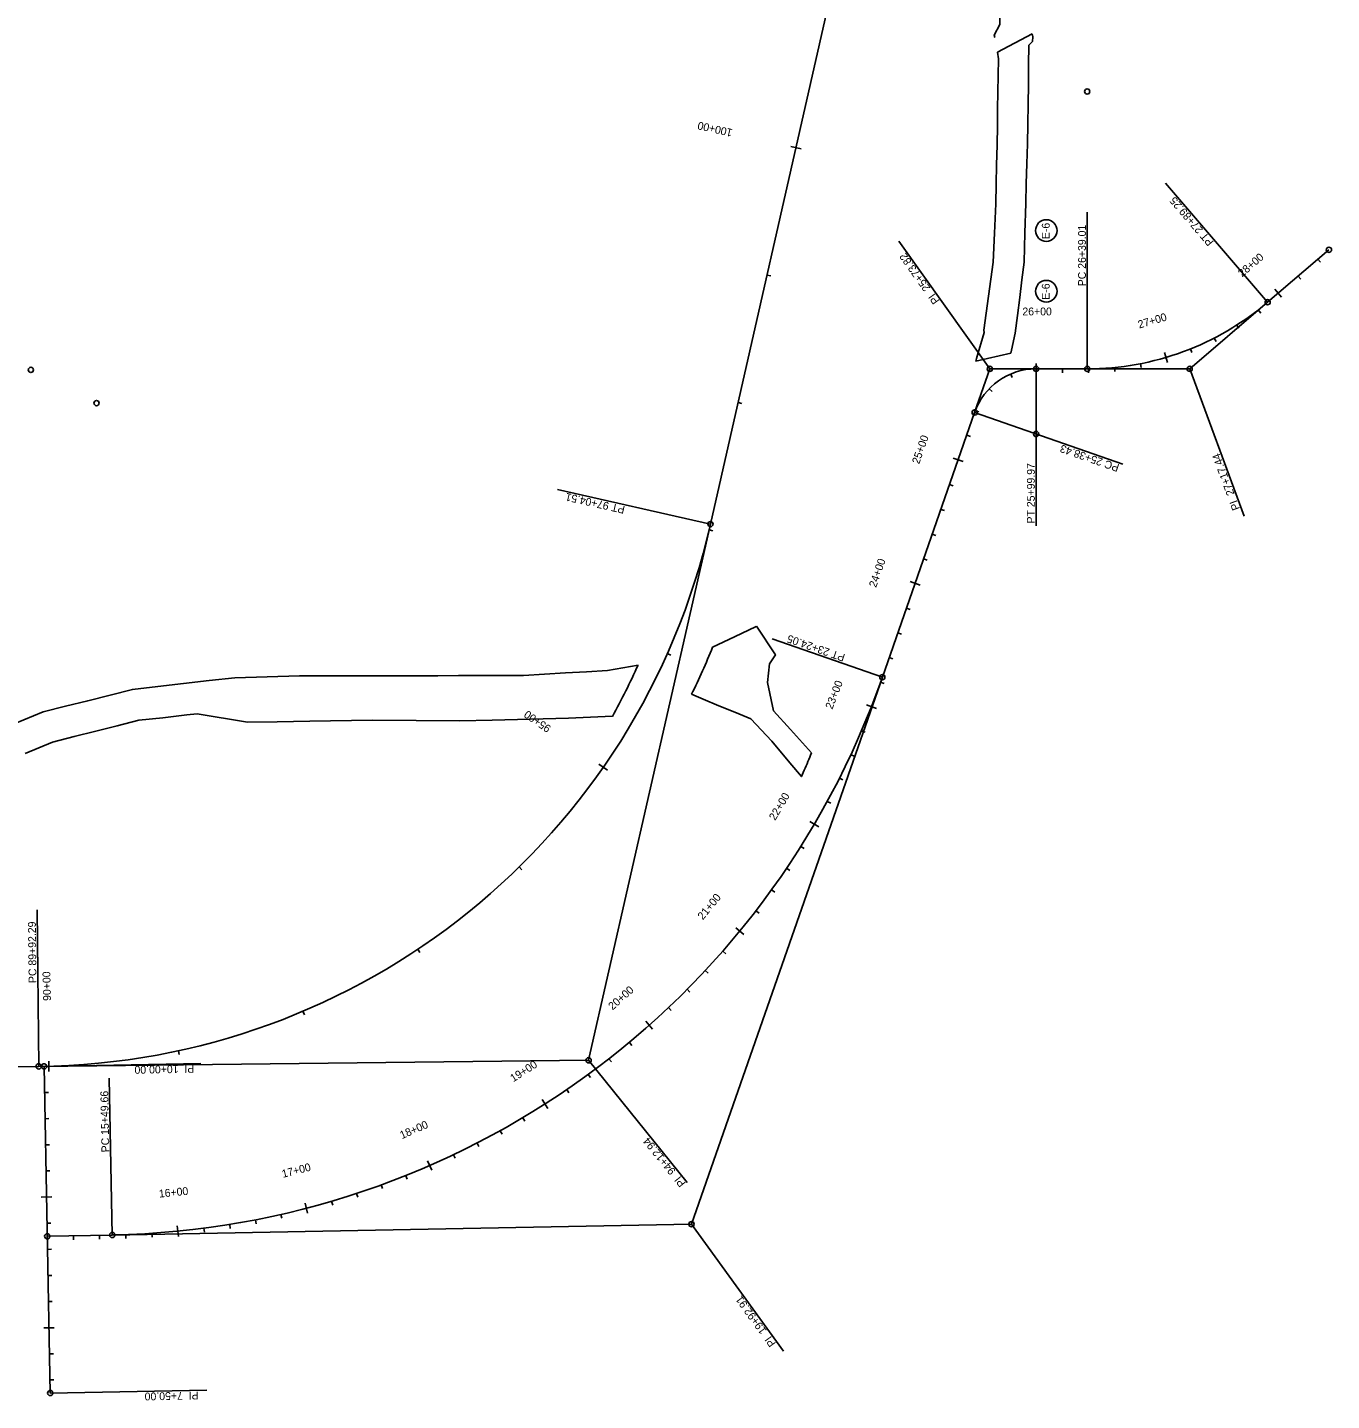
# Model space of a CAD drawing. Extents: x 1710760 to 1712722, y 548603 to 551099.
# Drawn here: x 1711724 to 1712722, y 548957 to 550007 of the extents above; entities that cross this region are included whole.
import ezdxf

# ---------------------------------------------------------------- set-up
doc = ezdxf.new("R2010")
doc.units = 0
for name, color, linetype in [('R_Draft', 7, 'Continuous'), ('R_Erosion', 7, 'Continuous'), ('R_Horz Alg', 7, 'Continuous'), ('R_Horz Alg Annot', 7, 'Continuous')]:
    doc.layers.add(name, color=color, linetype=linetype)

msp = doc.modelspace()

# ---------------------------------------------------------------- linework, layer by layer
at = {"layer": 'R_Draft'}
msp.add_line((1712466.4, 549988.4), (1712492.8, 550002.3), dxfattribs=at)
for points in [[(1712467.8, 550127.2), (1712467.8, 550116.5), (1712467.5, 550095.6), (1712466.2, 550089.2), (1712466.5, 550075.5), (1712466.7, 550061.9), (1712467.1, 550048.8), (1712467.4, 550035.7), (1712467.8, 550022.6), (1712468.1, 550009.5), (1712463.8, 550001.4), (1712464.3, 549999.7)], [(1712492.8, 550002.3), (1712493.5, 550000), (1712493.1, 549996.5), (1712490.4, 549993.8), (1712490.2, 549978.7), (1712490, 549963.6), (1712489.9, 549948.5), (1712489.7, 549933.4), (1712489.3, 549918.2), (1712488.9, 549903), (1712488.4, 549887.9), (1712488, 549872.7), (1712487.4, 549850.2), (1712486.8, 549827.8), (1712485.1, 549814.2), (1712483.4, 549800.6), (1712481.7, 549787), (1712480, 549773.4), (1712477.1, 549760.5), (1712476.5, 549758)], [(1712449.8, 549752), (1712450.4, 549754), (1712456.2, 549773.8), (1712456, 549775.6), (1712457.7, 549788.6), (1712459.5, 549801.6), (1712461.3, 549814.6), (1712463, 549827.6), (1712464.1, 549850), (1712465.1, 549872.4), (1712465.4, 549887.3), (1712465.7, 549902.3), (1712466, 549917.2), (1712466.3, 549932.2), (1712466.5, 549945), (1712466.7, 549957.7), (1712467, 549970.5), (1712467.2, 549983.2), (1712466.4, 549988.4)], [(1712476.5, 549758), (1712449.8, 549752)], [(1712282, 549549.2), (1712281.7, 549549), (1712265.1, 549541), (1712248.5, 549533.1), (1712248.5, 549533.1)], [(1712292, 549520.4), (1712296.5, 549527.2), (1712282, 549549.2)], [(1711714.3, 549474.5), (1711736.5, 549483.6), (1711753.5, 549487.9), (1711770.5, 549492.2), (1711787.6, 549496.5), (1711804.6, 549500.8), (1711824.2, 549503.1), (1711843.8, 549505.3), (1711863.4, 549507.6), (1711883.1, 549509.8), (1711907.8, 549510.4), (1711932.5, 549511.1), (1711947.3, 549511.1), (1711962.1, 549511.1), (1711976.9, 549511.2), (1711991.6, 549511.2), (1712007.2, 549511.3), (1712022.8, 549511.3), (1712038.4, 549511.3), (1712054, 549511.4), (1712078.8, 549511.4), (1712103.7, 549511.4), (1712119.8, 549512.4), (1712135.9, 549513.4), (1712152, 549514.4), (1712168.1, 549515.4), (1712191.4, 549519.5)], [(1712324, 549452.3), (1712321.8, 549454.8), (1712308.1, 549470.1), (1712295.1, 549484.4), (1712290.5, 549506), (1712292, 549520.4)], [(1712232.3, 549497.1), (1712241.2, 549493.4), (1712253.3, 549488.4), (1712265.4, 549483.4), (1712277.6, 549478.4), (1712293.7, 549461.2), (1712307.5, 549444.7), (1712316.5, 549434.1), (1712318.5, 549439.1)], [(1712171.9, 549480.3), (1712138.3, 549478.9), (1712079.9, 549477.2), (1712055.1, 549476.9), (1712021.6, 549477.1), (1711988.1, 549477.2), (1711940.4, 549476.5), (1711915.5, 549476), (1711892.7, 549475.7), (1711854.2, 549482.1), (1711846.3, 549481.3), (1711828, 549479.2), (1711809.6, 549477.2), (1711793.1, 549473), (1711776.6, 549468.8), (1711760.1, 549464.7), (1711743.6, 549460.5), (1711722.5, 549451.8)]]:
    msp.add_lwpolyline(points, dxfattribs=at)
for centre, radius, start, end in [((1711727, 549745.3), 563, 333.8405, 337.855), ((1711548.7, 549815.5), 707.7, 331.7192, 335.2717), ((1711895.9, 549621), 460.2, 336.7051, 338.4954)]:
    msp.add_arc(centre, radius, start, end, dxfattribs=at)
at = {"layer": 'R_Erosion'}
for centre in [(1712503.7, 549851.9), (1712503.7, 549805.5)]:
    msp.add_circle(centre, 8.26, dxfattribs=at)
at = {"layer": 'R_Horz Alg'}
for p, q in [((1712246.8, 549627.3), (1712450.8, 550525.8)), ((1712673, 549797.1), (1712719.9, 549837.2)), ((1712495.9, 549746.1), (1712535, 549746.1)), ((1712378.3, 549510.2), (1712448.9, 549712.7)), ((1711391.8, 549208.5), (1711733, 549212.4)), ((1711741.8, 548962.5), (1711737.1, 549212.4)), ((1711739.5, 549082.4), (1711789.2, 549083.4))]:
    msp.add_line(p, q, dxfattribs=at)
for centre, radius, start, end in [((1712535, 549958.3), 212.2, 270, 310.5648), ((1712495.9, 549696.3), 49.8, 90, 160.7734), ((1711727, 549745.3), 533, 270.6428, 347.2066), ((1711777.2, 549719.9), 636.6, 271.0787, 340.7734)]:
    msp.add_arc(centre, radius, start, end, dxfattribs=at)
at = {"layer": 'R_Horz Alg Annot'}
for p, q in [((1712613.4, 549746.1), (1712673, 549797.1)), ((1712448.9, 549712.7), (1712460.5, 549746.1)), ((1712460.5, 549746.1), (1712495.9, 549746.1)), ((1712535, 549746.1), (1712613.4, 549746.1)), ((1712153.6, 549217.1), (1712246.8, 549627.3)), ((1712232.3, 549091.7), (1712378.3, 549510.2)), ((1711733, 549212.4), (1712153.6, 549217.1)), ((1711789.2, 549083.4), (1712232.3, 549091.7))]:
    msp.add_line(p, q, dxfattribs=at)
for points in [[(1712308.3, 549916.3), (1712316.1, 549914.5)], [(1712673, 549797.1), (1712594.9, 549888.2)], [(1712535, 549746.1), (1712535, 549866.1)], [(1712460.5, 549746.1), (1712391, 549843.9)], [(1712713.5, 549827.8), (1712711.5, 549830.1)], [(1712293, 549817.3), (1712290.1, 549817.9)], [(1712698.3, 549814.8), (1712696.3, 549817.1)], [(1712678.5, 549807.1), (1712683.7, 549801)], [(1712667.7, 549788.8), (1712665.8, 549791.2)], [(1712651.1, 549777.1), (1712649.5, 549779.6)], [(1712615.1, 549758.6), (1712614, 549761.3)], [(1712633.6, 549767), (1712632.2, 549769.7)], [(1712496, 549750.1), (1712496, 549742.1)], [(1712576.3, 549747.1), (1712575.7, 549750)], [(1712594, 549758.6), (1712596.3, 549750.9)], [(1712477.7, 549739.4), (1712476.5, 549742.1)], [(1712495.9, 549746.1), (1712495.9, 549626.1)], [(1712516, 549743.1), (1712516, 549746.1)], [(1712536, 549743.1), (1712536, 549746.1)], [(1712556.2, 549744.1), (1712555.9, 549747.1)], [(1712613.4, 549746.1), (1712655, 549633.5)], [(1712462.3, 549728.8), (1712460.1, 549730.9)], [(1712270.8, 549719.7), (1712267.9, 549720.4)], [(1712448.9, 549712.7), (1712562.2, 549673.1)], [(1712452.2, 549713.1), (1712449.4, 549714.1)], [(1712445.6, 549694.3), (1712442.8, 549695.3)], [(1712432.4, 549677.7), (1712440, 549675.1)], [(1712432.5, 549656.5), (1712429.6, 549657.5)], [(1712246.8, 549627.3), (1712129.8, 549653.9)], [(1712425.9, 549637.6), (1712423.1, 549638.6)], [(1712248.7, 549622.2), (1712245.8, 549622.9)], [(1712419.3, 549618.7), (1712416.5, 549619.7)], [(1712412.7, 549599.8), (1712409.9, 549600.8)], [(1712399.5, 549583.3), (1712407.1, 549580.6)], [(1712399.5, 549562.1), (1712396.7, 549563.1)], [(1712378.3, 549510.2), (1712294, 549539.6)], [(1712393, 549543.2), (1712390.1, 549544.2)], [(1712216.6, 549527.1), (1712213.8, 549528.3)], [(1712386.4, 549524.3), (1712383.5, 549525.3)], [(1712379.8, 549505.4), (1712376.9, 549506.4)], [(1712366.2, 549489.1), (1712373.7, 549486.2)], [(1712365.1, 549468), (1712362.4, 549469.2)], [(1712356.9, 549449.7), (1712354.2, 549450.9)], [(1712161.5, 549443.6), (1712168.1, 549439)], [(1712348.1, 549431.6), (1712345.5, 549432.9)], [(1712338.8, 549413.8), (1712336.2, 549415.2)], [(1712322.9, 549399.8), (1712329.8, 549395.8)], [(1712318.5, 549379.1), (1712315.9, 549380.7)], [(1712102.5, 549362.8), (1712100.4, 549365)], [(1712307.5, 549362.3), (1712305, 549364)], [(1712296, 549345.8), (1712293.6, 549347.6)], [(1711733, 549212.4), (1711731.7, 549332.3)], [(1712284, 549329.7), (1712281.6, 549331.5)], [(1712266.1, 549318.4), (1712272.3, 549313.3)], [(1712024.6, 549299.5), (1712022.9, 549302)], [(1712258.5, 549298.6), (1712256.2, 549300.6)], [(1712245, 549283.7), (1712242.8, 549285.8)], [(1712231.1, 549269.3), (1712229, 549271.4)], [(1712216.7, 549255.2), (1712214.7, 549257.4)], [(1711936.2, 549251.8), (1711935, 549254.6)], [(1712197.3, 549246.9), (1712202.6, 549240.9)], [(1711840.5, 549221.5), (1711839.8, 549224.4)], [(1712186.7, 549228.5), (1712184.8, 549230.8)], [(1711737.1, 549212.4), (1711857, 549214.7)], [(1711740.6, 549216.5), (1711740.8, 549208.5)], [(1712153.6, 549217.1), (1712229, 549123.7)], [(1712171, 549215.9), (1712169.2, 549218.3)], [(1711789.2, 549083.4), (1711786.9, 549203.4)], [(1712155, 549203.8), (1712153.2, 549206.2)], [(1712138.6, 549192.2), (1712136.9, 549194.7)], [(1711740.4, 549192.5), (1711737.4, 549192.4)], [(1712118.1, 549187), (1712122.4, 549180.2)], [(1711740.8, 549172.5), (1711737.8, 549172.4)], [(1712104.8, 549170.5), (1712103.2, 549173.1)], [(1712087.4, 549160.5), (1712085.9, 549163.1)], [(1711741.2, 549152.5), (1711738.2, 549152.4)], [(1712069.6, 549151), (1712068.3, 549153.7)], [(1712030.5, 549140.2), (1712033.7, 549132.9)], [(1712051.6, 549142.1), (1712050.3, 549144.8)], [(1711741.6, 549132.5), (1711738.6, 549132.4)], [(1711996, 549118.9), (1711995, 549121.7)], [(1712014.8, 549126), (1712013.7, 549128.8)], [(1711734.9, 549112.4), (1711742.9, 549112.5)], [(1711957.9, 549106.3), (1711957, 549109.2)], [(1711977, 549112.3), (1711976.1, 549115.1)], [(1711919, 549096.2), (1711918.3, 549099.1)], [(1711936.7, 549107.7), (1711938.7, 549100)], [(1711742.3, 549092.5), (1711739.3, 549092.4)], [(1711839, 549090.3), (1711839.8, 549082.3)], [(1711859.7, 549085.6), (1711859.3, 549088.6)], [(1711879.5, 549088.5), (1711879.1, 549091.5)], [(1711899.3, 549092), (1711898.7, 549095)], [(1712232.3, 549091.7), (1712302.7, 548994.5)], [(1711759.6, 549079.8), (1711759.5, 549082.8)], [(1711779.6, 549080.2), (1711779.5, 549083.2)], [(1711799.6, 549080.7), (1711799.5, 549083.7)], [(1711819.7, 549081.7), (1711819.5, 549084.7)], [(1711742.7, 549072.5), (1711739.7, 549072.4)], [(1711743.1, 549052.5), (1711740.1, 549052.4)], [(1711743.4, 549032.5), (1711740.4, 549032.4)], [(1711736.8, 549012.4), (1711744.8, 549012.5)], [(1711744.2, 548992.5), (1711741.2, 548992.5)], [(1711744.6, 548972.5), (1711741.6, 548972.5)], [(1711741.8, 548962.5), (1711861.7, 548964.7)]]:
    msp.add_lwpolyline(points, dxfattribs=at)
for centre in [(1712535, 549958.3), (1712719.9, 549837.2), (1712673, 549797.1), (1711727, 549745.3), (1712460.5, 549746.1), (1712495.9, 549746.1), (1712535, 549746.1), (1712613.4, 549746.1), (1711777.2, 549719.9), (1712448.9, 549712.7), (1712495.9, 549696.3), (1712246.8, 549627.3), (1712378.3, 549510.2), (1711733, 549212.4), (1711737.1, 549212.4), (1712153.6, 549217.1), (1712232.3, 549091.7), (1711739.5, 549082.4), (1711789.2, 549083.4), (1711741.8, 548962.5)]:
    msp.add_circle(centre, 2, dxfattribs=at)

# ---------------------------------------------------------------- texts
at = {"layer": 'R_Erosion'}
for p in [(1712506.3, 549845.4), (1712506.3, 549799)]:
    msp.add_text('E-6 ', height=6, rotation=90, dxfattribs=at).set_placement(p)
at = {"layer": 'R_Horz Alg Annot'}
for s, rotation, p in [('100+00', 167.2066, (1712264.1, 549929.4)), ('PT 27+89.25', 130.5648, (1712632.1, 549843.3)), ('PC 26+39.01', 90, (1712534, 549809.3)), ('PI  25+73.82', 125.3867, (1712422.3, 549798.2)), ('28+00', 40.5648, (1712653.5, 549816)), ('27+00', 16.4663, (1712574.8, 549776.9)), ('25+00', 70.7734, (1712406.4, 549672.8)), ('PC 25+38.43', 160.7734, (1712560, 549672.8)), ('PI  27+17.44', 110.2824, (1712651.9, 549639.1)), ('PT 25+99.97', 90, (1712494.9, 549627.8)), ('PT 97+04.51', 167.2066, (1712181.8, 549641)), ('24+00', 70.7734, (1712373.5, 549578.4)), ('PT 23+24.05', 160.7734, (1712350.3, 549527.6)), ('23+00', 68.6088, (1712340, 549485.2)), ('95+00', 145.2214, (1712125.4, 549472.3)), ('22+00', 59.6088, (1712296.3, 549400.1)), ('21+00', 50.6088, (1712241, 549324.1)), ('PC 89+92.29', 90.6428, (1711731.3, 549276.2)), ('90+00', 91.4714, (1711742.4, 549262.6)), ('20+00', 41.6088, (1712171.9, 549255.1)), ('19+00', 32.6088, (1712096, 549200.2)), ('PI  10+00.00', 181.0787, (1711851.9, 549213.6)), ('PC 15+49.66', 91.0787, (1711787, 549146.7)), ('18+00', 23.6088, (1712010.8, 549156.7)), ('PI  94+12.94', 128.9247, (1712228.2, 549123.1)), ('17+00', 14.6088, (1711919.8, 549127.1)), ('16+00', 5.6088, (1711825.2, 549112)), ('PI  19+92.91', 125.926, (1712297.2, 549000.5)), ('PI  7+50.00', 181.0787, (1711855.2, 548963.6))]:
    msp.add_text(s, height=6, rotation=rotation, dxfattribs=at).set_placement(p)
msp.add_text('26+00', height=6, dxfattribs=at).set_placement((1712485.4, 549787))

doc.saveas('drawing.dxf')
